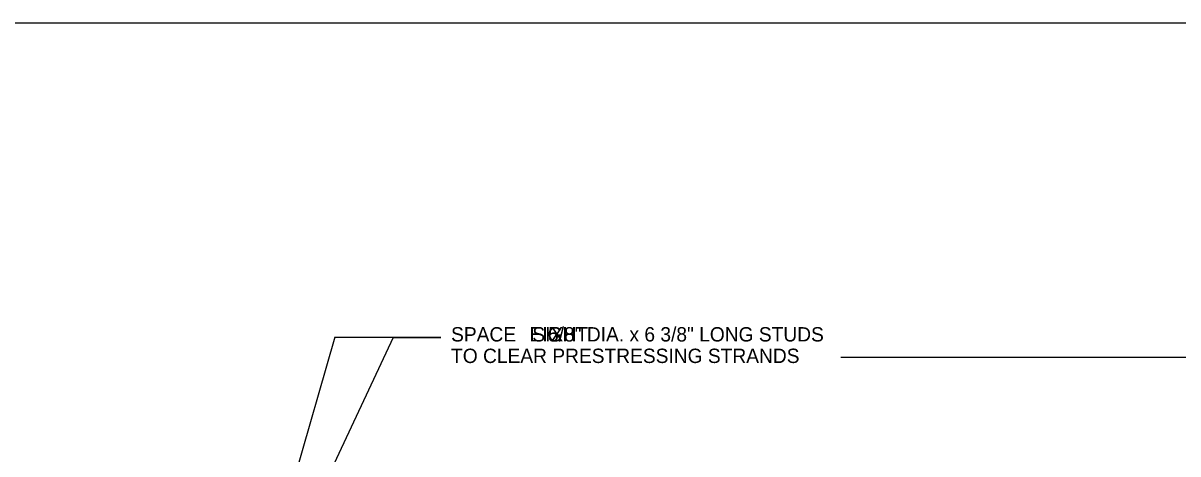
# Model space of a CAD drawing. Extents: x 997.7 to 1009.7, y 1494.3 to 1503.3.
# Drawn here: x 1000.459 to 1003.815, y 1501.374 to 1502.625 of the extents above; entities that cross this region are included whole.
import ezdxf

# ---------------------------------------------------------------- set-up
doc = ezdxf.new("R2010")
doc.units = 0
for name, color, linetype in [('Level 1', 7, 'Continuous'), ('Level 15', 7, 'Continuous'), ('Level 2', 7, 'Continuous'), ('Level 4', 7, 'Continuous'), ('Level 5', 7, 'Continuous'), ('Level 6', 7, 'Continuous'), ('Level 7', 7, 'Continuous'), ('Level 8', 7, 'Continuous')]:
    doc.layers.add(name, color=color, linetype=linetype)

msp = doc.modelspace()

# ---------------------------------------------------------------- linework, layer by layer
at = {"layer": 'Level 1'}
msp.add_line((1009.1944, 1502.6253), (998.7369, 1502.6253), dxfattribs=at)
at = {"layer": 'Level 15'}
for q in [(1001.0705, 1500.6928), (1001.6726, 1501.7132)]:
    msp.add_line((1001.3651, 1501.7132), q, dxfattribs=at)
at = {"layer": 'Level 2'}
msp.add_line((1003.9556, 1501.6536), (1002.8354, 1501.6536), dxfattribs=at)
at = {"layer": 'Level 4'}
for q in [(1001.0705, 1500.7223), (1001.6731, 1501.7116)]:
    msp.add_line((1001.5349, 1501.7116), q, dxfattribs=at)
at = {"layer": 'Level 5'}
for q in [(1001.0705, 1500.7223), (1001.6731, 1501.7116)]:
    msp.add_line((1001.5349, 1501.7116), q, dxfattribs=at)
at = {"layer": 'Level 6'}
for q in [(1001.0705, 1500.7223), (1001.6731, 1501.7116)]:
    msp.add_line((1001.5349, 1501.7116), q, dxfattribs=at)
at = {"layer": 'Level 7'}
for q in [(1001.0705, 1500.7223), (1001.6731, 1501.7116)]:
    msp.add_line((1001.5349, 1501.7116), q, dxfattribs=at)
at = {"layer": 'Level 8'}
for q in [(1001.0705, 1500.7223), (1001.6731, 1501.7116)]:
    msp.add_line((1001.5349, 1501.7116), q, dxfattribs=at)

# ---------------------------------------------------------------- texts
at = {"layer": 'Level 15'}
msp.add_text('EIGHT', height=0.04167, dxfattribs=at).set_placement((1001.9308, 1501.7004))
at = {"layer": 'Level 2'}
for s, p in [('SPACE      5/8" DIA. x 6 3/8" LONG STUDS', (1001.7028, 1501.7004)), ('TO CLEAR PRESTRESSING STRANDS', (1001.7028, 1501.6379))]:
    msp.add_text(s, height=0.041667, dxfattribs=at).set_placement(p)
at = {"layer": 'Level 4'}
msp.add_text('SIX', height=0.04167, dxfattribs=at).set_placement((1001.9389, 1501.7004))
at = {"layer": 'Level 5'}
msp.add_text('SIX', height=0.04167, dxfattribs=at).set_placement((1001.9389, 1501.7004))
at = {"layer": 'Level 6'}
msp.add_text('SIX', height=0.04167, dxfattribs=at).set_placement((1001.9389, 1501.7004))
at = {"layer": 'Level 7'}
msp.add_text('SIX', height=0.04167, dxfattribs=at).set_placement((1001.9389, 1501.7004))
at = {"layer": 'Level 8'}
msp.add_text('SIX', height=0.04167, dxfattribs=at).set_placement((1001.9389, 1501.7004))

doc.saveas('drawing.dxf')
